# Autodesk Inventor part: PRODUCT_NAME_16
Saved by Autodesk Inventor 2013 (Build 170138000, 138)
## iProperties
Created: 2012-12
Part Number: PRODUCT_NAME_16
Material: Générique
Document SubType Name: Modeling
Designer: jost thierry
Density: 1 g/cm^3
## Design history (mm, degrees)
node "PRODUCT_NAME_161"
node "PRODUCT_NAME_16"
node "Base1"
